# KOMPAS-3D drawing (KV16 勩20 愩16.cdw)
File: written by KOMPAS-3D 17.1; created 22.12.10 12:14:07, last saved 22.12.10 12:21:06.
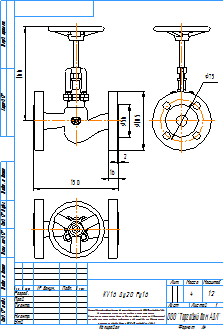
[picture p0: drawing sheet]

Title block, sheet 1: name: KV16 Ду20 Ру16; mass: 4; sheets: 1; sheet format: A4; stored path: \\adlc.lan\data\АДЛ_ПКД\3D-модели\ADL production\Вентили ГРАНВЕНТ\KV16\KOMPAS 2D\KV16 Ду20 Ру16.cdw

Views: Спереди 1
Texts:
  Рама для чертежей
  Лит-Масса-Масштаб
  Материал-Предприятие
  Масштаб
  Изм.
  Лист
  № докум.
  Подп.
  Дата
  Лит.
  Разраб.
  Пров.
  Т.контр.
  Листов
  Внимание! Данный продукт является объектом авторского права ООО «Торговый Дом АДЛ».
  Запрещается изменение, копирование, распространение
  (в том числе путем копирования на другие сайты и ресурсы в Интернете)
  или любое иное использование информации и объектов без предварительного
  согласия правообладателя (ООО «Торговый Дом АДЛ»).
  Н.контр.
  Утв.
  ООО "Торговый дом АДЛ"
  Изменение
  Номер документа
  Подпись
  Обозначение документа
  Наименование изделия
  Масса изделия по ГОСТ 2.109-73
  Порядковый номер листа
  Общее количество листов в документе
  Характер работы, выполненной лицом, подписавшим документ
  Наименование или индекс предприятия, выпускающего документ
  Инв. № подл.
  Подп. и дата
  Взам. инв. №
  Инв. № дубл.
  Инвентарный номер подлинника по ГОСТ 2.501-68
  Подпись принявшего подлинник в отдел технической документации
  Инвентарный номер подлинника, взамен которого выпущен данный подлинник
  Инвентарный номер дубликата по ГОСТ 2.502-68
  Подпись принявшего дубликат в отдел технической документации
  Справ. №
  Перв. примен.
  Обозначение документа, взамен или на основании которого выпущен данный документ
  Обозначение документа, в котором впервые записан данный документ
  Подпись лица, копировавшего чертеж
  Обозначение формата листа
  !Рама для чертежа
Dimensions and other numbers on the sheet: 56; 105; 150; 2; 16; 75; 166; 1:2; 1; 4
